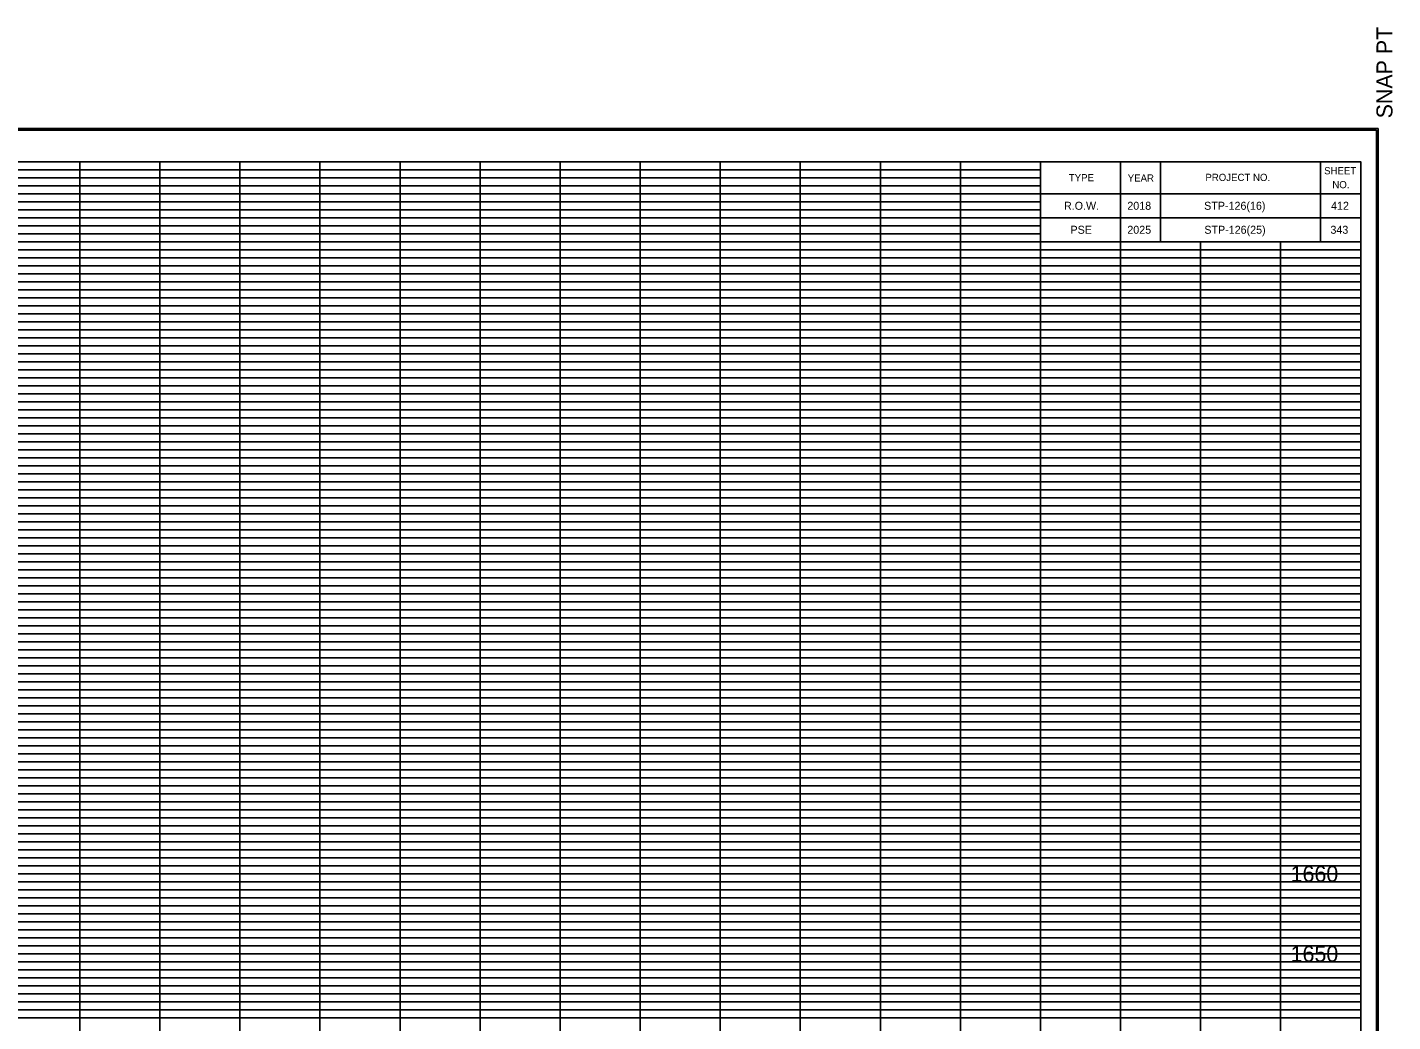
# Model space of a CAD drawing. Extents: x 980 to 1324, y 978 to 1767.
# Drawn here: x 1153.4 to 1324, y 1642.5 to 1766.8 of the extents above; entities that cross this region are included whole.
import ezdxf

# ---------------------------------------------------------------- set-up
doc = ezdxf.new("R2010")
doc.units = 0
for name, color, linetype in [('DESIGN - SCRATCH - User 1', 7, 'Continuous'), ('DESIGN - SHEET - Corner Text', 7, 'Continuous'), ('DESIGN - SHEET - Light Grid', 7, 'Continuous'), ('DESIGN - SHEET - Linework', 7, 'Continuous'), ('DESIGN - SHEET - Plot Shape', 7, 'Continuous'), ('DESIGN - TYPICAL - Finished Grade and Subgrade', 7, 'Continuous')]:
    doc.layers.add(name, color=color, linetype=linetype)

# ---------------------------------------------------------------- blocks, each defined once
blk = doc.blocks.new('XSTSHT')
at = {"layer": 'DESIGN - SCRATCH - User 1'}
for p, q in [((28.5, 20.45), (28.5, 20.45)), ((29.24, 20.45), (29.24, 20.45)), ((30.49, 20.45), (30.49, 20.45)), ((31.74, 20.45), (31.74, 20.45)), ((28.5, 20.15), (28.5, 20.15)), ((29.24, 20.15), (29.24, 20.15)), ((30.49, 20.15), (30.49, 20.15)), ((31.74, 20.15), (31.74, 20.15))]:
    blk.add_line(p, q, dxfattribs=at)
at = {"layer": 'DESIGN - SHEET - Light Grid'}
for p, q in [((8, 20.9), (16, 20.9)), ((16, 20.9), (24, 20.9)), ((24, 20.9), (28, 20.9)), ((8, 20.8), (16, 20.8)), ((8, 20.7), (16, 20.7)), ((16, 20.8), (24, 20.8)), ((16, 20.7), (24, 20.7)), ((24, 20.8), (28, 20.8)), ((24, 20.7), (28, 20.7)), ((8, 20.6), (16, 20.6)), ((8, 20.5), (16, 20.5)), ((16, 20.6), (24, 20.6)), ((16, 20.5), (24, 20.5)), ((24, 20.6), (28, 20.6)), ((24, 20.5), (28, 20.5)), ((8, 20.4), (16, 20.4)), ((8, 20.3), (16, 20.3)), ((16, 20.4), (24, 20.4)), ((16, 20.3), (24, 20.3)), ((24, 20.4), (28, 20.4)), ((24, 20.3), (28, 20.3)), ((8, 20.2), (16, 20.2)), ((16, 20.2), (24, 20.2)), ((24, 20.2), (28, 20.2)), ((8, 20.1), (16, 20.1)), ((16, 20.1), (24, 20.1)), ((24, 20.1), (28, 20.1)), ((8, 19.9), (16, 19.9)), ((8, 19.8), (16, 19.8)), ((16, 19.9), (24, 19.9)), ((16, 19.8), (24, 19.8)), ((24, 19.9), (32, 19.9)), ((24, 19.8), (32, 19.8)), ((8, 19.7), (16, 19.7)), ((16, 19.7), (24, 19.7)), ((24, 19.7), (32, 19.7)), ((8, 19.6), (16, 19.6)), ((8, 19.5), (16, 19.5)), ((16, 19.6), (24, 19.6)), ((16, 19.5), (24, 19.5)), ((24, 19.6), (32, 19.6)), ((24, 19.5), (32, 19.5)), ((8, 19.4), (16, 19.4)), ((8, 19.3), (16, 19.3)), ((16, 19.4), (24, 19.4)), ((16, 19.3), (24, 19.3)), ((24, 19.4), (32, 19.4)), ((24, 19.3), (32, 19.3)), ((8, 19.2), (16, 19.2)), ((16, 19.2), (24, 19.2)), ((24, 19.2), (32, 19.2)), ((8, 19.1), (16, 19.1)), ((16, 19.1), (24, 19.1)), ((24, 19.1), (32, 19.1)), ((8, 18.9), (16, 18.9)), ((8, 18.8), (16, 18.8)), ((16, 18.9), (24, 18.9)), ((16, 18.8), (24, 18.8)), ((24, 18.9), (32, 18.9)), ((24, 18.8), (32, 18.8)), ((8, 18.7), (16, 18.7)), ((8, 18.6), (16, 18.6)), ((16, 18.7), (24, 18.7)), ((16, 18.6), (24, 18.6)), ((24, 18.7), (32, 18.7)), ((24, 18.6), (32, 18.6)), ((8, 18.5), (16, 18.5)), ((16, 18.5), (24, 18.5)), ((24, 18.5), (32, 18.5)), ((8, 18.4), (16, 18.4)), ((8, 18.3), (16, 18.3)), ((16, 18.4), (24, 18.4)), ((16, 18.3), (24, 18.3)), ((24, 18.4), (32, 18.4)), ((24, 18.3), (32, 18.3)), ((8, 18.2), (16, 18.2)), ((8, 18.1), (16, 18.1)), ((16, 18.2), (24, 18.2)), ((16, 18.1), (24, 18.1)), ((24, 18.2), (32, 18.2)), ((24, 18.1), (32, 18.1)), ((8, 17.9), (16, 17.9)), ((8, 17.8), (16, 17.8)), ((16, 17.9), (24, 17.9)), ((16, 17.8), (24, 17.8)), ((24, 17.9), (32, 17.9)), ((24, 17.8), (32, 17.8)), ((8, 17.7), (16, 17.7)), ((8, 17.6), (16, 17.6)), ((16, 17.7), (24, 17.7)), ((16, 17.6), (24, 17.6)), ((24, 17.7), (32, 17.7)), ((24, 17.6), (32, 17.6)), ((8, 17.5), (16, 17.5)), ((8, 17.4), (16, 17.4)), ((16, 17.5), (24, 17.5)), ((16, 17.4), (24, 17.4)), ((24, 17.5), (32, 17.5)), ((24, 17.4), (32, 17.4)), ((8, 17.3), (16, 17.3)), ((16, 17.3), (24, 17.3)), ((24, 17.3), (32, 17.3)), ((8, 17.2), (16, 17.2)), ((8, 17.1), (16, 17.1)), ((16, 17.2), (24, 17.2)), ((16, 17.1), (24, 17.1)), ((24, 17.2), (32, 17.2)), ((24, 17.1), (32, 17.1)), ((8, 16.9), (16, 16.9)), ((16, 16.9), (24, 16.9)), ((24, 16.9), (32, 16.9)), ((8, 16.8), (16, 16.8)), ((16, 16.8), (24, 16.8)), ((24, 16.8), (32, 16.8)), ((8, 16.7), (16, 16.7)), ((8, 16.6), (16, 16.6)), ((16, 16.7), (24, 16.7)), ((16, 16.6), (24, 16.6)), ((24, 16.7), (32, 16.7)), ((24, 16.6), (32, 16.6)), ((8, 16.5), (16, 16.5)), ((8, 16.4), (16, 16.4)), ((16, 16.5), (24, 16.5)), ((16, 16.4), (24, 16.4)), ((24, 16.5), (32, 16.5)), ((24, 16.4), (32, 16.4)), ((8, 16.3), (16, 16.3)), ((16, 16.3), (24, 16.3)), ((24, 16.3), (32, 16.3)), ((8, 16.2), (16, 16.2)), ((8, 16.1), (16, 16.1)), ((16, 16.2), (24, 16.2)), ((16, 16.1), (24, 16.1)), ((24, 16.2), (32, 16.2)), ((24, 16.1), (32, 16.1)), ((8, 15.9), (16, 15.9)), ((16, 15.9), (24, 15.9)), ((24, 15.9), (32, 15.9)), ((8, 15.8), (16, 15.8)), ((8, 15.7), (16, 15.7)), ((16, 15.8), (24, 15.8)), ((16, 15.7), (24, 15.7)), ((24, 15.8), (32, 15.8)), ((24, 15.7), (32, 15.7)), ((8, 15.6), (16, 15.6)), ((16, 15.6), (24, 15.6)), ((24, 15.6), (32, 15.6)), ((8, 15.5), (16, 15.5)), ((8, 15.4), (16, 15.4)), ((16, 15.5), (24, 15.5)), ((16, 15.4), (24, 15.4)), ((24, 15.5), (32, 15.5)), ((24, 15.4), (32, 15.4)), ((8, 15.3), (16, 15.3)), ((8, 15.2), (16, 15.2)), ((16, 15.3), (24, 15.3)), ((16, 15.2), (24, 15.2)), ((24, 15.3), (32, 15.3)), ((24, 15.2), (32, 15.2)), ((8, 15.1), (16, 15.1)), ((16, 15.1), (24, 15.1)), ((24, 15.1), (32, 15.1)), ((8, 14.9), (16, 14.9)), ((16, 14.9), (24, 14.9)), ((24, 14.9), (32, 14.9)), ((8, 14.8), (16, 14.8)), ((8, 14.7), (16, 14.7)), ((16, 14.8), (24, 14.8)), ((16, 14.7), (24, 14.7)), ((24, 14.8), (32, 14.8)), ((24, 14.7), (32, 14.7)), ((8, 14.6), (16, 14.6)), ((8, 14.5), (16, 14.5)), ((16, 14.6), (24, 14.6)), ((16, 14.5), (24, 14.5)), ((24, 14.6), (32, 14.6)), ((24, 14.5), (32, 14.5)), ((8, 14.4), (16, 14.4)), ((16, 14.4), (24, 14.4)), ((24, 14.4), (32, 14.4)), ((8, 14.3), (16, 14.3)), ((8, 14.2), (16, 14.2)), ((16, 14.3), (24, 14.3)), ((16, 14.2), (24, 14.2)), ((24, 14.3), (32, 14.3)), ((24, 14.2), (32, 14.2)), ((8, 14.1), (16, 14.1)), ((16, 14.1), (24, 14.1)), ((24, 14.1), (32, 14.1)), ((8, 13.9), (16, 13.9)), ((16, 13.9), (24, 13.9)), ((24, 13.9), (32, 13.9)), ((8, 13.8), (16, 13.8)), ((8, 13.7), (16, 13.7)), ((16, 13.8), (24, 13.8)), ((16, 13.7), (24, 13.7)), ((24, 13.8), (32, 13.8)), ((24, 13.7), (32, 13.7)), ((8, 13.6), (16, 13.6)), ((8, 13.5), (16, 13.5)), ((16, 13.6), (24, 13.6)), ((16, 13.5), (24, 13.5)), ((24, 13.6), (32, 13.6)), ((24, 13.5), (32, 13.5)), ((8, 13.4), (16, 13.4)), ((16, 13.4), (24, 13.4)), ((24, 13.4), (32, 13.4)), ((8, 13.3), (16, 13.3)), ((8, 13.2), (16, 13.2)), ((16, 13.3), (24, 13.3)), ((16, 13.2), (24, 13.2)), ((24, 13.3), (32, 13.3)), ((24, 13.2), (32, 13.2)), ((8, 13.1), (16, 13.1)), ((16, 13.1), (24, 13.1)), ((24, 13.1), (32, 13.1)), ((8, 12.9), (16, 12.9)), ((8, 12.8), (16, 12.8)), ((16, 12.9), (24, 12.9)), ((16, 12.8), (24, 12.8)), ((24, 12.9), (32, 12.9)), ((24, 12.8), (32, 12.8)), ((8, 12.7), (16, 12.7)), ((16, 12.7), (24, 12.7)), ((24, 12.7), (32, 12.7)), ((8, 12.6), (16, 12.6)), ((8, 12.5), (16, 12.5)), ((16, 12.6), (24, 12.6)), ((16, 12.5), (24, 12.5)), ((24, 12.6), (32, 12.6)), ((24, 12.5), (32, 12.5)), ((8, 12.4), (16, 12.4)), ((8, 12.3), (16, 12.3)), ((16, 12.4), (24, 12.4)), ((16, 12.3), (24, 12.3)), ((24, 12.4), (32, 12.4)), ((24, 12.3), (32, 12.3)), ((8, 12.2), (16, 12.2)), ((16, 12.2), (24, 12.2)), ((24, 12.2), (32, 12.2)), ((8, 12.1), (16, 12.1)), ((16, 12.1), (24, 12.1)), ((24, 12.1), (32, 12.1)), ((8, 11.9), (16, 11.9)), ((8, 11.8), (16, 11.8)), ((16, 11.9), (24, 11.9)), ((16, 11.8), (24, 11.8)), ((24, 11.9), (32, 11.9)), ((24, 11.8), (32, 11.8)), ((8, 11.7), (16, 11.7)), ((8, 11.6), (16, 11.6)), ((16, 11.7), (24, 11.7)), ((16, 11.6), (24, 11.6)), ((24, 11.7), (32, 11.7)), ((24, 11.6), (32, 11.6)), ((8, 11.5), (16, 11.5)), ((16, 11.5), (24, 11.5)), ((24, 11.5), (32, 11.5)), ((8, 11.4), (16, 11.4)), ((8, 11.3), (16, 11.3)), ((16, 11.4), (24, 11.4)), ((16, 11.3), (24, 11.3)), ((24, 11.4), (32, 11.4)), ((24, 11.3), (32, 11.3)), ((8, 11.2), (16, 11.2)), ((8, 11.1), (16, 11.1)), ((16, 11.2), (24, 11.2)), ((16, 11.1), (24, 11.1)), ((24, 11.2), (32, 11.2)), ((24, 11.1), (32, 11.1)), ((8, 10.9), (16, 10.9)), ((8, 10.8), (16, 10.8)), ((16, 10.9), (24, 10.9)), ((16, 10.8), (24, 10.8)), ((24, 10.9), (32, 10.9)), ((24, 10.8), (32, 10.8)), ((8, 10.7), (16, 10.7)), ((8, 10.6), (16, 10.6)), ((16, 10.7), (24, 10.7)), ((16, 10.6), (24, 10.6)), ((24, 10.7), (32, 10.7)), ((24, 10.6), (32, 10.6)), ((8, 10.5), (16, 10.5)), ((16, 10.5), (24, 10.5)), ((24, 10.5), (32, 10.5)), ((8, 10.4), (16, 10.4)), ((8, 10.3), (16, 10.3)), ((16, 10.4), (24, 10.4)), ((16, 10.3), (24, 10.3)), ((24, 10.4), (32, 10.4)), ((24, 10.3), (32, 10.3))]:
    blk.add_line(p, q, dxfattribs=at)
at = {"layer": 'DESIGN - SHEET - Linework'}
for p, q in [((-1.823, 21.414), (32.217, 21.414)), ((32.217, 21.414), (32.217, -0.414)), ((16, 0), (16, 21)), ((17, 0), (17, 21)), ((18, 0), (18, 21)), ((19, 0), (19, 21)), ((20, 0), (20, 21)), ((21, 0), (21, 21)), ((22, 0), (22, 21)), ((23, 0), (23, 21)), ((24, 0), (24, 21)), ((25, 0), (25, 21)), ((26, 0), (26, 21)), ((27, 0), (27, 21)), ((0, 20), (28, 20)), ((28, 0), (28, 20)), ((29, 0), (29, 20)), ((30, 0), (30, 20)), ((31, 0), (31, 20)), ((0, 19), (32, 19)), ((0, 18), (32, 18)), ((0, 17), (32, 17)), ((0, 16), (32, 16)), ((0, 15), (32, 15)), ((0, 14), (32, 14)), ((0, 13), (32, 13)), ((0, 12), (32, 12)), ((0, 11), (32, 11))]:
    blk.add_line(p, q, dxfattribs=at)
for points in [[(0, 21), (0, 0), (32, 0), (32, 21), (0, 21)], [(28, 21), (28, 20), (32, 20), (32, 21), (31.5, 21), (31.5, 20), (29.5, 20), (29.5, 21), (29, 21), (29, 20), (32, 20), (28, 20), (28, 20.3), (32, 20.3), (32, 20.6), (28, 20.6)]]:
    blk.add_lwpolyline(points, dxfattribs=at)
at = {"layer": 'DESIGN - SHEET - Plot Shape'}
for points in [[(-1.803, 21.394), (32.197, 21.394), (32.197, -0.394), (-1.803, -0.394)], [(-0.85, 21), (32, 21), (32, -0.25), (-0.85, -0.25)]]:
    blk.add_lwpolyline(points, close=True, dxfattribs=at)
at = {"layer": 'DESIGN - SHEET - Corner Text'}
blk.add_text('  SNAP PT', height=0.2, rotation=90, dxfattribs=at).set_placement((32.397, 21.394))
for s, p in [('TYPE', (28.354, 20.756)), ('YEAR', (29.09, 20.752)), ('PROJECT NO.', (30.06, 20.76)), ('SHEET', (31.543, 20.843)), ('NO.', (31.646, 20.669))]:
    blk.add_text(s, height=0.09, dxfattribs=at).set_placement(p)

msp = doc.modelspace()

# ---------------------------------------------------------------- linework, layer by layer
at = {"layer": 'DESIGN - SHEET - Plot Shape'}
msp.add_lwpolyline([(991.5, 1750), (1320, 1750), (1320, 1537.5), (991.5, 1537.5)], close=True, dxfattribs=at)

# ---------------------------------------------------------------- block references
at = {"layer": 'DESIGN - TYPICAL - Finished Grade and Subgrade', "xscale": 10, "yscale": 10}
msp.add_blockref('XSTSHT', (1000, 1540), dxfattribs=at)

# ---------------------------------------------------------------- texts
at = {"layer": 'DESIGN - SHEET - Corner Text'}
for s, height, p in [('R.O.W.', 1, (1282.94, 1744)), ('2018', 1, (1290.85, 1744)), ('STP-126(16)', 1, (1300.45, 1744)), ('412', 1, (1316.3, 1744)), ('PSE', 1, (1283.75, 1741)), ('2025', 1, (1290.85, 1741)), ('STP-126(25)', 1, (1300.47, 1741)), ('343', 1, (1316.22, 1741)), ('1660', 2, (1311.25, 1660)), ('1650', 2, (1311.25, 1650))]:
    msp.add_text(s, height=height, dxfattribs=at).set_placement(p)

doc.saveas('drawing.dxf')
